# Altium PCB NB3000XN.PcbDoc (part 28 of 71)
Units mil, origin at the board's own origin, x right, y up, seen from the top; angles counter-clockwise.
Board outline 9527.56 x 6929.77 mil, 6 copper layers (Top Layer, GND+SHIELD, MidLayer1, MidLayer2, P2 - 3V3+5V0, Bottom Layer), stack 62.375 mil thick; 832 components, 1027 nets, 4655 pads, 4981 vias.
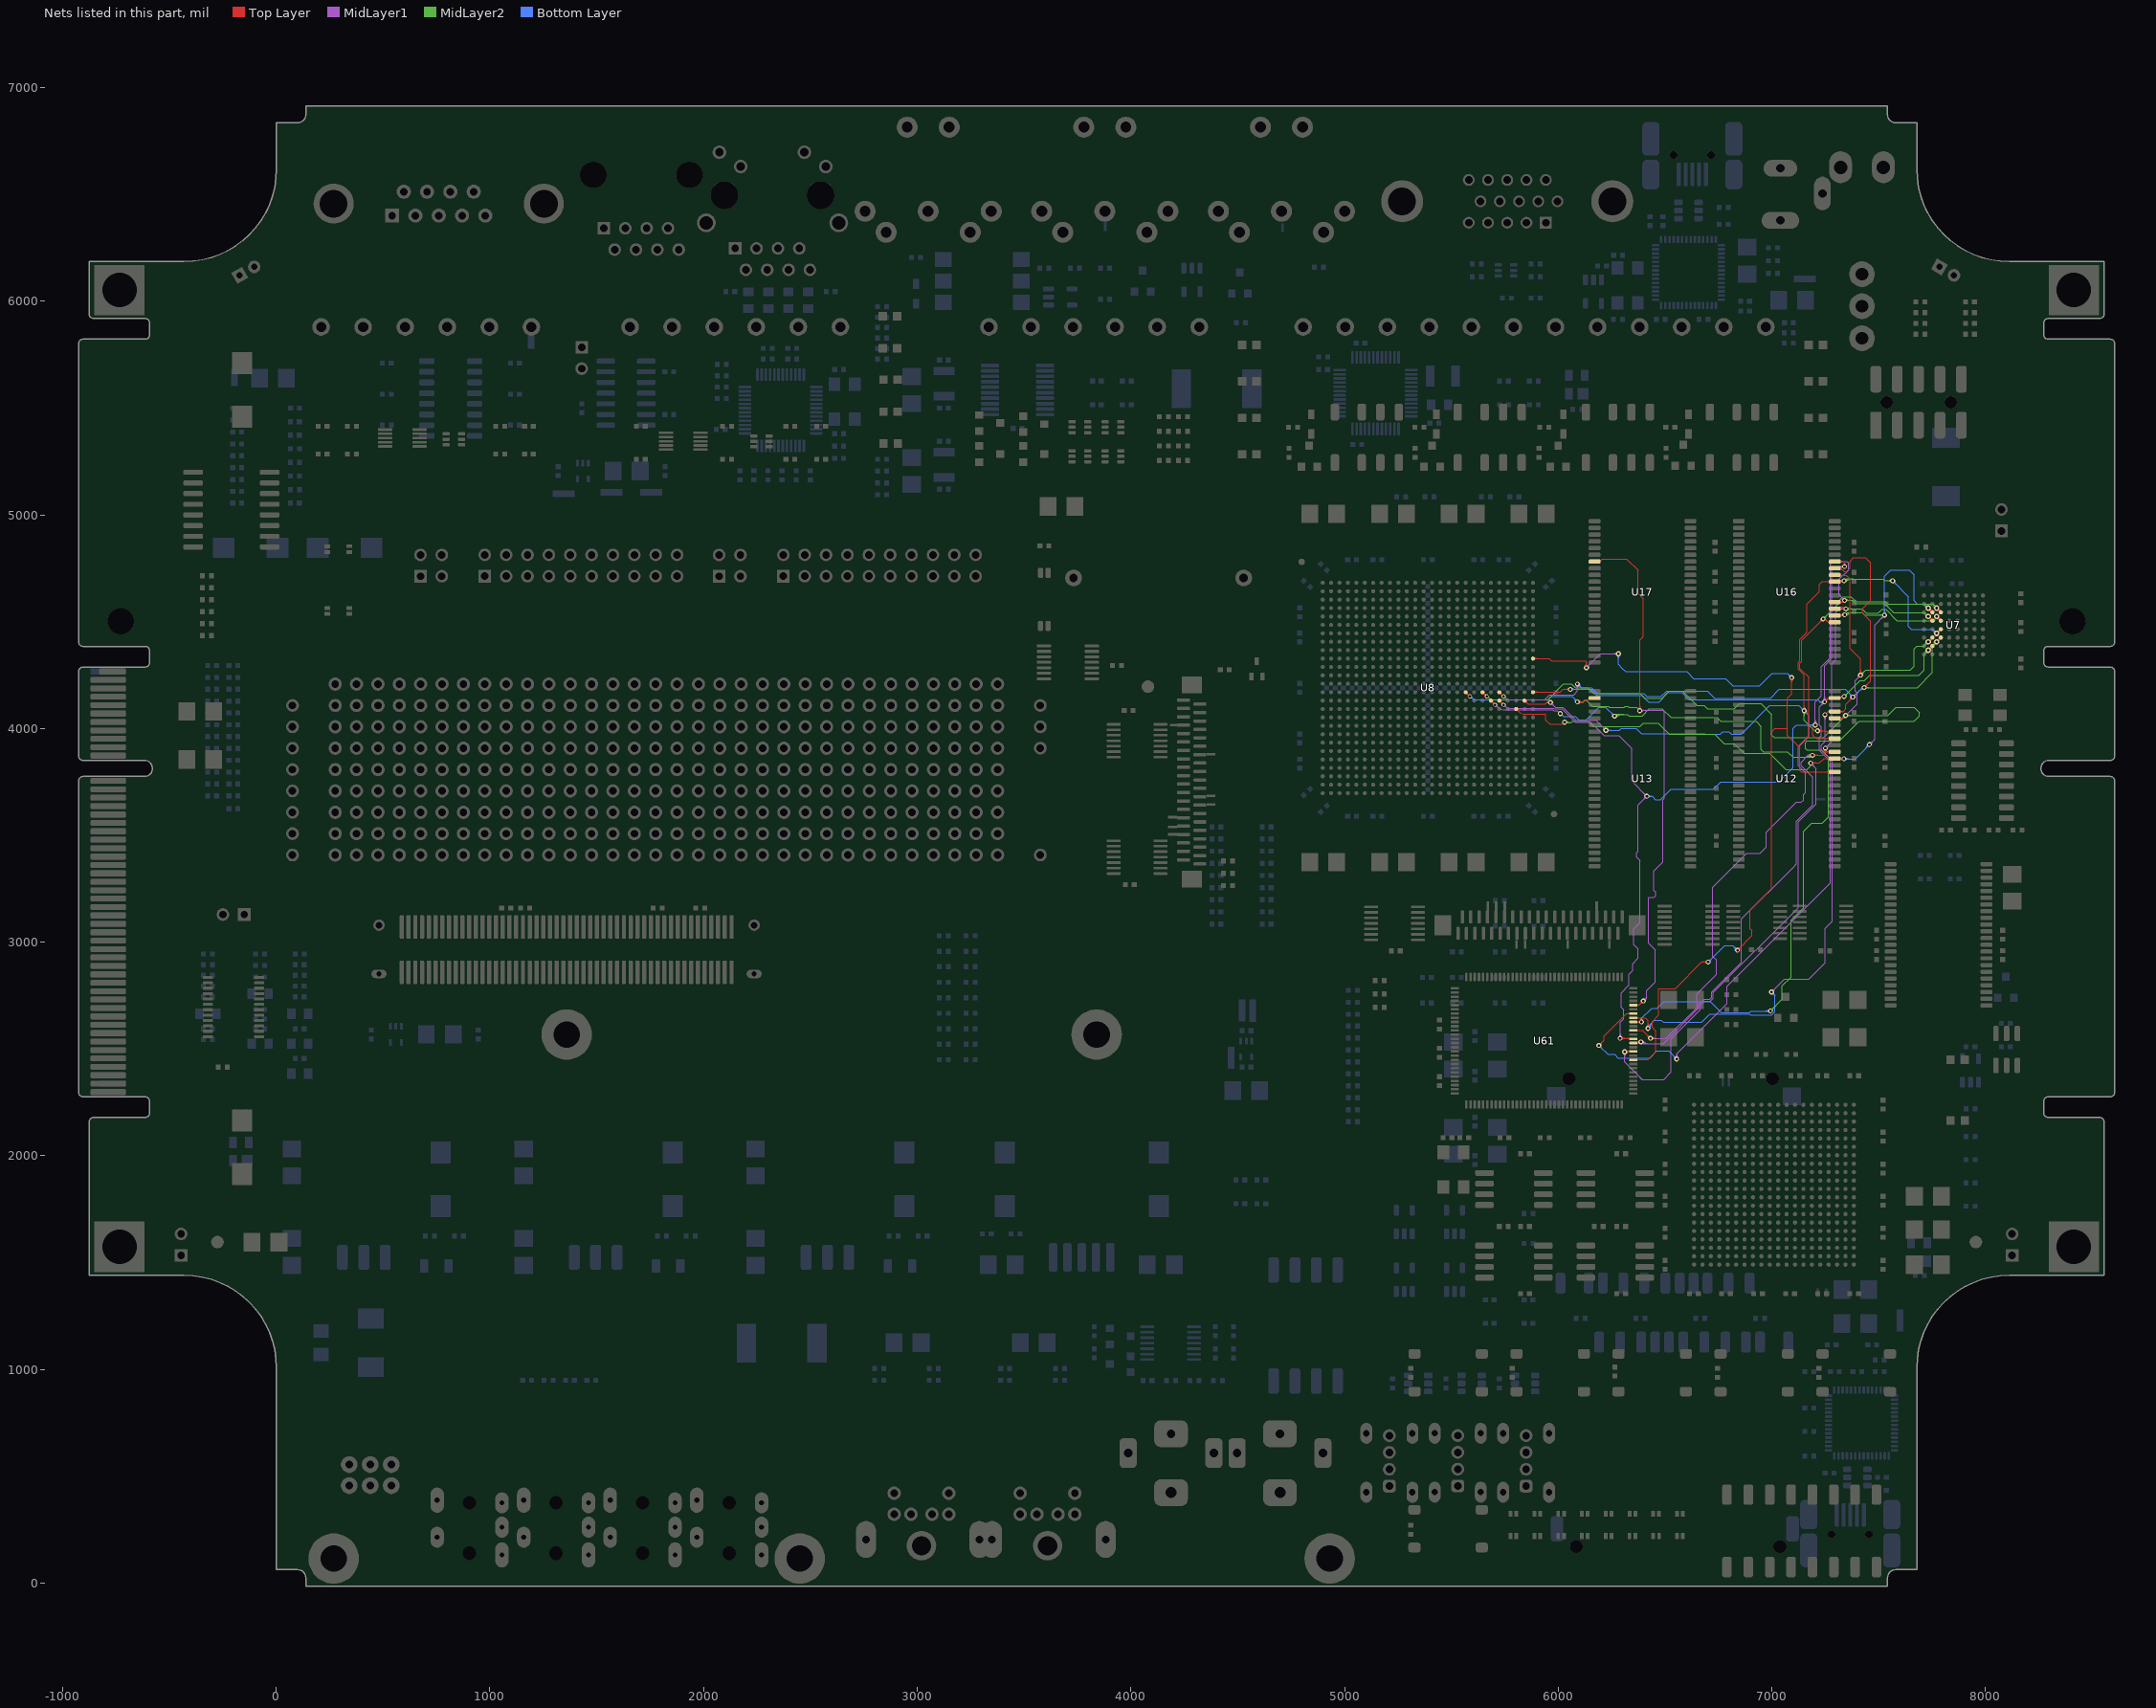
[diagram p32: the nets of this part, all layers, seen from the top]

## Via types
v1: diameter 23, hole 11.81, Top Layer to Bottom Layer, 3672 vias
v2: diameter 26, hole 11.81, Top Layer to Bottom Layer, 461 vias
v3: diameter 19, hole 11.81, Top Layer to Bottom Layer, tented both sides, 396 vias
v4: diameter 23.62, hole 11.81, Top Layer to Bottom Layer, 288 vias
v5: diameter 20, hole 11.81, Top Layer to Bottom Layer, 91 vias
v6: diameter 23, hole 11.81, Top Layer to Bottom Layer, tented both sides, 50 vias
v7: diameter 31, hole 11.81, Top Layer to Bottom Layer, 15 vias
v8: diameter 27.56, hole 11.81, Top Layer to Bottom Layer, tented both sides, 4 vias
v9: diameter 29, hole 11.81, Top Layer to Bottom Layer, 3 vias
v10: diameter 21, hole 11.81, Top Layer to Bottom Layer, 1 vias

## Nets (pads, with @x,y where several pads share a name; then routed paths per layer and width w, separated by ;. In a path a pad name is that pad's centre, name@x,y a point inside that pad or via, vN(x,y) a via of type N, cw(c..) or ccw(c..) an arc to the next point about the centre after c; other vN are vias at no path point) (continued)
DB_MEM.BUS_D8: U7.F3 U8.K26 U12.42 U16.29 U61.47 | length 6471.7
  Top Layer w4: U8.K26@5882.13,4327.8 5910,4327.8 5920,4327.8 5957.5,4327.8 5968.42,4316.87 6128.13,4316.87 6131.86,4313.14 v1(6131.86,4284.37) ; U8.K26@5887.43,4322.49 cw(c5900.23,4309.69) 5900.23,4327.8 cw(c5900.23,4345.9) U8.K26@5887.43,4333.1 ; v1@6125.14,4291.09 ccw(c6108.92,4307.31) 6131.86,4307.31 ccw(c6154.79,4307.31) v1@6138.57,4291.09 ; v1@6127.97,4288.26 ccw(c6118.58,4297.65) 6131.86,4297.65 ccw(c6145.14,4297.65) v1@6135.75,4288.26 ; U61.47@6356.86,2450.04 6420.04,2450.04 6456.86,2486.86 6456.86,2583.37 6440.19,2600.04 6440.19,2627.37 6471.19,2658.37 6471.19,2781.71 6472.86,2783.37 6548.52,2783.37 6672.52,2907.37 v1(6702.19,2907.37) ; U61.47@6367.95,2446.63 cw(c6376.19,2438.39) 6376.19,2450.04 ; U61.47@6367.95,2452.28 ccw(c6373.37,2457.7) 6373.37,2450.04 ; v1@6695.47,2900.66 ccw(c6679.26,2884.44) 6679.26,2907.37 ccw(c6679.26,2930.31) v1@6695.47,2914.09 ; v1@6698.3,2903.49 ccw(c6688.91,2894.1) 6688.91,2907.37 ccw(c6688.91,2920.65) v1@6698.3,2911.26 ; v1(6838.86,2962.37) 6906.86,3030.37 6906.86,3055 6898.52,3063.33 6898.52,3150.04 6998.52,3250.04 6998.52,3983.37 7015.19,4000.04 7073.52,4000.04 ; v1@6838.86,2967.87 ccw(c6838.86,2981.15) 6848.25,2971.76 ccw(c6857.64,2962.37) v1@6844.36,2962.37 ; v1@6838.86,2971.87 ccw(c6838.86,2994.81) 6855.07,2978.59 ccw(c6871.29,2962.37) v1@6848.36,2962.37 ; v1@7086.47,4231.99 cw(c7070.26,4215.77) 7093.19,4215.77 cw(c7116.13,4215.77) v1@7099.91,4231.99 ; v1@7089.3,4234.82 cw(c7079.91,4225.43) 7093.19,4225.43 cw(c7106.47,4225.43) v1@7097.08,4234.82 ; v1(7093.19,4238.71) 7093.19,4161.37 7073.52,4141.71 7073.52,4000.04 ; v1@7230.69,4513.04 cw(c7207.76,4513.04) 7223.97,4496.82 cw(c7240.19,4480.61) v1@7240.19,4503.54 ; v1@7234.69,4513.04 cw(c7221.41,4513.04) 7230.8,4503.65 cw(c7240.19,4494.26) v1@7240.19,4507.54 ; v1@7240.33,4511.55 cw(c7242.12,4492.78) 7255.45,4506.11 ; v1@7240.71,4507.57 cw(c7243.17,4481.82) 7261.46,4500.11 ; U16.29@7269.85,4494.4 ccw(c7263.3,4490.79) 7263.3,4498.27 ; U16.29@7269.85,4502.13 cw(c7263.3,4505.75) 7263.3,4498.27 ; U12.42@7271.19,3790.84 ccw(c7257.54,3777.18) 7257.54,3796.5 ccw(c7257.54,3815.81) U12.42@7271.19,3802.15 ; U12.42@7294.41,3796.5 7139.86,3796.5 7131.86,3804.5 7131.86,3908.37 ; U16.29@7294.41,4498.27 7263.3,4498.27 ; 5899.85,4327.8 ccw(c5899.85,4310.07) 5887.32,4322.6 cw(c5899.85,4310.07) 5899.85,4327.8 ; 5899.85,4327.8 cw(c5899.85,4345.52) 5887.32,4332.99 ccw(c5899.85,4345.52) 5899.85,4327.8 ; 7073.52,4000.04 7073.52,3966.71 7123.19,3917.04 ; 7123.19,3917.04 7131.86,3908.37 ; 7123.19,3917.04 7131.86,3908.37 ; 7123.19,3917.04 7173.52,3967.37 7173.52,4240.04 7131.86,4281.71 7131.86,4306.04 7140.19,4314.37 7140.19,4413.04 v1(7240.19,4513.04) 7248.52,4513.04 7263.3,4498.27
  Top Layer w8: v2@7771.26,4554.74 cw(c7771.26,4533.01) 7786.62,4548.38 cw(c7801.99,4563.74) v2@7780.26,4563.74 ; v2(7771.26,4563.74) U7.F3@7790.95,4544.06 ; U7.F3@7784.95,4544.06 ccw(c7770.46,4544.06) 7780.7,4554.3 ccw(c7790.95,4564.54) U7.F3@7790.95,4550.06
  MidLayer1 w4: v1(6131.86,4284.37) 6197.52,4350.04 v1(6281.86,4350.04) ; v1@6131.86,4289.87 ccw(c6131.86,4303.15) 6141.25,4293.76 ccw(c6150.64,4284.37) v1@6137.36,4284.37 ; v1@6131.86,4293.87 ccw(c6131.86,4316.81) 6148.07,4300.59 ccw(c6164.29,4284.37) v1@6141.36,4284.37 ; v1@6275.14,4343.32 ccw(c6258.92,4327.11) 6258.92,4350.04 ccw(c6258.92,4372.98) v1@6275.14,4356.76 ; v1@6277.97,4346.15 ccw(c6268.58,4336.76) 6268.58,4350.04 ccw(c6268.58,4363.32) v1@6277.97,4353.93
  MidLayer2 w4: v1(7240.19,4513.04) 7316.14,4588.99 7316.14,4601.99 7331.86,4617.71 7370.61,4617.71 7394.61,4593.71 7531.23,4593.71 7541.57,4583.37 7751.63,4583.37 v2(7771.26,4563.74) ; v1@7240.19,4518.54 ccw(c7240.19,4531.82) 7249.58,4522.43 ccw(c7258.97,4513.04) v1@7245.69,4513.04 ; v1@7240.19,4522.54 ccw(c7240.19,4545.48) 7256.41,4529.26 ccw(c7272.63,4513.04) v1@7249.69,4513.04 ; v2@7760.26,4563.74 ccw(c7733.7,4563.74) 7752.48,4582.52 ccw(c7771.26,4601.3) v2@7771.26,4574.74 ; v2@7764.26,4563.74 ccw(c7747.36,4563.74) 7759.31,4575.69 ccw(c7771.26,4587.64) v2@7771.26,4570.74
  Bottom Layer w4: v1@6275.14,4343.32 cw(c6258.92,4327.11) 6281.86,4327.11 cw(c6304.79,4327.11) v1@6288.57,4343.32 ; v1@6277.97,4346.15 cw(c6268.58,4336.76) 6281.86,4336.76 cw(c6295.14,4336.76) v1@6285.75,4346.15 ; v1(6281.86,4350.04) 6281.86,4300.04 6298.52,4283.37 6315.52,4266.37 6602.19,4266.37 6634.19,4234.37 6783.84,4234.37 6818.17,4200.04 6941.86,4200.04 7000.19,4258.37 7073.52,4258.37 v1(7093.19,4238.71) ; v1(6702.19,2907.37) 6774.52,2979.71 6778.52,2983.71 6817.52,2983.71 v1(6838.86,2962.37) ; v1@6702.19,2912.87 ccw(c6702.19,2926.15) 6711.58,2916.76 ccw(c6720.97,2907.37) v1@6707.69,2907.37 ; v1@6702.19,2916.87 ccw(c6702.19,2939.81) 6718.41,2923.59 ccw(c6734.63,2907.37) v1@6711.69,2907.37 ; v1@6829.36,2962.37 ccw(c6806.42,2962.37) 6822.64,2978.59 ccw(c6838.86,2994.81) v1@6838.86,2971.87 ; v1@6833.36,2962.37 ccw(c6820.08,2962.37) 6829.47,2971.76 ccw(c6838.86,2981.15) v1@6838.86,2967.87 ; v1@7083.69,4238.71 ccw(c7060.76,4238.71) 7076.97,4254.93 ccw(c7093.19,4271.14) v1@7093.19,4248.21 ; v1@7087.69,4238.71 ccw(c7074.41,4238.71) 7083.8,4248.1 ccw(c7093.19,4257.49) v1@7093.19,4244.21
DB_MEM.BUS_D9: U7.G3 U8.T24 U12.44 U16.30 U61.49 | length 6555.2
  Top Layer w4: U8.T24@5803.39,4084.23 cw(c5803.39,4066.51) 5815.92,4079.04 ; U8.T24@5810.73,4091.57 ccw(c5828.45,4091.57) 5815.92,4079.04 ; v1(6030,4030) 6020,4020 5961.9,4020 5942.36,4039.54 5942.36,4063.22 5937.86,4067.71 5920,4067.71 5910,4067.71 5843.27,4067.71 cw(c5843.27,4106.39) 5815.92,4079.04 ; v1(6311.19,2487.04) 6312.98,2488.83 U61.49@6351.93,2488.83 ; v1@6315.08,2483.15 cw(c6328.78,2469.45) 6328.78,2488.83 ; v1@6317.91,2480.32 cw(c6338.43,2459.8) U61.49@6338.43,2488.83 ; v1@6317.91,2493.76 ccw(c6329.82,2505.67) 6329.82,2488.83 ; U61.49@6335.91,2486 ccw(c6329.08,2479.17) 6329.08,2488.83 ccw(c6329.08,2498.48) U61.49@6335.91,2491.65 ; v1(7181.86,3838.71) 7223.71,3838.71 7244.49,3859.49 U12.44@7294.41,3859.49 ; v1@7185.75,3834.82 cw(c7195.14,3825.43) 7195.14,3838.71 cw(c7195.14,3851.99) v1@7185.75,3842.6 ; v1@7188.57,3831.99 cw(c7204.79,3815.77) 7204.79,3838.71 cw(c7204.79,3861.64) v1@7188.57,3845.43 ; U12.44@7271.19,3853.83 ccw(c7257.54,3840.17) 7257.54,3859.49 ccw(c7257.54,3878.8) U12.44@7271.19,3865.15 ; U12.44@7291.3,3859.49 7332.52,3859.49 7333.64,3858.37 v1(7337.52,3858.37) ; U16.30@7294.41,4529.76 7335.14,4529.76 7340.52,4524.37 v1(7340.52,4532.71) ; U16.30@7310.48,4529.76 ccw(c7310.48,4562.75) v1@7333.81,4539.43 ; U12.44@7311.9,3859.49 cw(c7311.9,3832.75) v1@7330.81,3851.66 ; U12.44@7317.28,3859.49 ccw(c7317.28,3878.62) v1@7330.81,3865.09 ; U12.44@7317.63,3853.83 cw(c7331.28,3840.18) 7331.28,3859.49 cw(c7331.28,3878.8) U12.44@7317.63,3865.15 ; U16.30@7317.63,4524.11 cw(c7331.28,4510.45) 7331.28,4529.76 cw(c7331.28,4549.08) U16.30@7317.63,4535.42 ; U16.30@7320.14,4529.76 ccw(c7320.14,4553.09) v1@7336.64,4536.6 ; U12.44@7321.56,3859.49 cw(c7321.56,3842.41) v1@7333.64,3854.49 ; 7324.7,4529.76 cw(c7324.7,4516.88) v1@7333.81,4525.99
  Top Layer w8: v2@7731.89,4554.74 cw(c7731.89,4533.01) 7747.25,4548.38 cw(c7762.62,4563.74) v2@7740.89,4563.74 ; v2(7731.89,4563.74) U7.G3@7751.58,4544.06 ; U7.G3@7745.58,4544.06 ccw(c7731.09,4544.06) 7741.33,4554.3 ccw(c7751.58,4564.54) U7.G3@7751.58,4550.06
  MidLayer1 w4: v1@6304.47,2480.32 cw(c6288.26,2464.11) 6311.19,2464.11 cw(c6334.13,2464.11) v1@6317.91,2480.32 ; v1@6306.86,2482.71 v1(6311.19,2487.04) 6311.19,2438.81 6391.63,2358.37 ; v1@6307.3,2483.15 cw(c6297.91,2473.76) 6311.19,2473.76 cw(c6324.47,2473.76) v1@6315.08,2483.15 ; 6381.4,2368.6 6391.96,2358.04 6493.88,2358.04 6529.19,2393.35 6529.19,2547.37 6665.19,2683.37 6665.19,2705.39 6685.17,2725.37 6712.84,2725.37 ; 6695.19,2725.04 6712.5,2725.04 6712.84,2725.37 ; v1@7181.86,3829.21 cw(c7181.86,3806.27) 7198.07,3822.49 cw(c7214.29,3838.71) v1@7191.36,3838.71 ; v1@7181.86,3833.21 cw(c7181.86,3819.93) 7191.25,3829.32 cw(c7200.64,3838.71) v1@7187.36,3838.71 ; v1(7181.86,3838.71) 7206.86,3813.71 7206.86,3670 7206.86,3647.06 7123.52,3563.73 7123.52,3541.71 7123.52,3535 7123.52,3161.37 6725.86,2763.71 6725.86,2738.39 6712.84,2725.37 ; v1(7456.86,3925.04) 7481.86,3950.04 7481.86,4484.71 v1(7527.86,4530.71) ; v1@7456.86,3930.54 ccw(c7456.86,3943.82) 7466.25,3934.43 ccw(c7475.64,3925.04) v1@7462.36,3925.04 ; v1@7456.86,3934.54 ccw(c7456.86,3957.48) 7473.07,3941.26 ccw(c7489.29,3925.04) v1@7466.36,3925.04 ; v1@7518.36,4530.71 cw(c7495.42,4530.71) 7511.64,4514.49 cw(c7527.86,4498.27) v1@7527.86,4521.21 ; v1@7522.36,4530.71 cw(c7509.08,4530.71) 7518.47,4521.32 cw(c7527.86,4511.93) v1@7527.86,4525.21
  MidLayer2 w4: v1(6030,4030) 6040,4030 6041.29,4028.71 6060.52,4028.71 6065.19,4033.37 6140.19,4033.37 6163.19,4010.37 6382.52,4010.37 6397.52,4025.37 6467.67,4025.37 6518.33,3974.71 6732.19,3974.71 6776.9,3930 6825,3930 6871.63,3883.37 6990.19,3883.37 7065.19,3808.37 7165.19,3808.37 7181.86,3825.04 v1(7181.86,3838.71) ; v1@6033.89,4033.89 ccw(c6046.4,4046.4) 6046.4,4028.71 ; v1@6036.72,4023.28 cw(c6049.82,4010.18) 6049.82,4028.71 ; v1@6036.72,4036.72 ccw(c6056.05,4056.05) 6056.05,4028.71 ; v1@7338.76,4534.48 cw(c7356.22,4517.02) 7356.22,4541.71 ; v1(7340.52,4532.71) 7349.52,4541.71 7423.52,4541.71 7434.52,4530.71 v1(7527.86,4530.71) ; v1@7341.58,4531.65 cw(c7365.87,4507.36) 7365.87,4541.71 ; v1@7344.41,4528.82 cw(c7375.53,4497.7) 7375.53,4541.71 ; v1@7347.24,4525.99 cw(c7385.19,4488.04) 7385.19,4541.71 ; v1@7521.14,4523.99 ccw(c7504.92,4507.77) 7504.92,4530.71 ccw(c7504.92,4553.64) v1@7521.14,4537.43 ; v1@7523.97,4526.82 ccw(c7514.58,4517.43) 7514.58,4530.71 ccw(c7514.58,4543.99) v1@7523.97,4534.6
  Bottom Layer w4: v1(7337.52,3858.37) 7390.19,3858.37 v1(7456.86,3925.04) ; v1@7341.41,3854.49 cw(c7350.8,3845.1) 7350.8,3858.37 cw(c7350.8,3871.65) v1@7341.41,3862.26 ; v1@7344.24,3851.66 cw(c7360.46,3835.44) 7360.46,3858.37 cw(c7360.46,3881.31) v1@7344.24,3865.09 ; v1@7447.36,3925.04 cw(c7424.42,3925.04) 7440.64,3908.82 cw(c7456.86,3892.61) v1@7456.86,3915.54 ; v1@7451.36,3925.04 cw(c7438.08,3925.04) 7447.47,3915.65 cw(c7456.86,3906.26) v1@7456.86,3919.54 ; v1@7521.14,4537.43 ccw(c7504.92,4553.64) 7527.86,4553.64 ccw(c7550.79,4553.64) v1@7534.57,4537.43 ; v1@7523.97,4534.6 ccw(c7514.58,4543.99) 7527.86,4543.99 ccw(c7541.14,4543.99) v1@7531.75,4534.6 ; v1(7527.86,4530.71) 7527.86,4712.71 7556.86,4741.71 7644.19,4741.71 7665.19,4720.71 7665.19,4597.71 7679.52,4583.37 7712.26,4583.37 v2(7731.89,4563.74) ; v2@7720.89,4563.74 ccw(c7694.33,4563.74) 7713.11,4582.52 ccw(c7731.89,4601.3) v2@7731.89,4574.74 ; v2@7724.89,4563.74 ccw(c7707.99,4563.74) 7719.94,4575.69 ccw(c7731.89,4587.64) v2@7731.89,4570.74
DB_MEM.BUS_D10: U7.F4 U8.R21 U12.45 U16.31 U61.51 | length 6324.8
  Top Layer w4: U8.R21@5685.28,4123.44 cw(c5685.28,4105.34) 5698.08,4118.14 cw(c5710.88,4130.94) U8.R21@5692.78,4130.94 ; U8.R21@5685.28,4123.6 cw(c5685.28,4105.88) 5697.81,4118.41 cw(c5710.34,4130.94) U8.R21@5692.62,4130.94 ; U8.R21@5685.28,4130.94 v3(5704.96,4111.26) ; U61.51@6361.54,2528.2 ccw(c6361.54,2558.84) v1@6383.29,2537.25 ; U61.51@6367.95,2525.37 cw(c6374.78,2518.54) 6374.78,2528.2 cw(c6374.78,2537.85) U61.51@6367.95,2531.02 ; 6371.15,2528.2 ccw(c6371.15,2549.3) v1@6386.13,2534.43 ; 6376.76,2528.2 cw(c6376.76,2522.94) v1@6380.47,2526.66 ; v1@6380.45,2540.07 cw(c6351.93,2568.37) U61.51@6351.93,2528.2 v1@6384.04,2528.2 ; v1(7190.19,3875.04) 7241.25,3875.04 7250.52,3884.32 ; v1@7194.08,3871.15 cw(c7203.47,3861.76) 7203.47,3875.04 cw(c7203.47,3888.32) v1@7194.08,3878.93 ; v1@7196.91,3868.32 cw(c7213.13,3852.11) 7213.13,3875.04 cw(c7213.13,3897.98) v1@7196.91,3881.76 ; v1@7243.81,3901.66 cw(c7227.59,3885.44) 7250.52,3885.44 cw(c7273.46,3885.44) v1@7257.24,3901.66 ; v1@7246.64,3904.49 cw(c7237.25,3895.1) 7250.52,3895.1 cw(c7263.8,3895.1) v1@7254.41,3904.49 ; v1(7250.52,3908.37) 7250.52,3884.32 ; U12.45@7271.19,3885.33 ccw(c7257.54,3871.67) 7257.54,3890.98 ccw(c7257.54,3910.3) U12.45@7271.19,3896.64 ; U12.45@7294.41,3890.98 7257.19,3890.98 7250.52,3884.32 ; U16.31@7299.86,4566.71 v1@7340.52,4566.71 ; U16.31@7308.16,4566.71 cw(c7308.16,4521.01) v1@7340.47,4553.32 ; U16.31@7311.97,4561.26 cw(c7323.54,4551.7) 7323.54,4566.71 ; U16.31@7315.05,4558.71 cw(c7332.03,4544.69) 7332.03,4566.71 ; U16.31@7317.82,4566.71 cw(c7317.82,4530.67) v1@7343.3,4556.15 ; U16.31@7318.14,4556.16 cw(c7340.52,4537.67) v1@7340.52,4566.71 ; 7327.47,4566.71 cw(c7327.47,4540.32) v1@7346.13,4558.98 ; 7337.13,4566.71 cw(c7337.13,4549.98) v1@7348.96,4561.81 ; v1(7347.19,4560.04) v1@7340.52,4566.71 ; 5692.16,4124.06 cw(c5679.35,4111.26) 5697.46,4111.26 ccw(c5679.35,4111.26) 5692.16,4124.06 ; 5692.16,4124.06 ccw(c5704.96,4136.87) 5704.96,4118.76 cw(c5704.96,4136.87) 5692.16,4124.06
  Top Layer w8: v2@7771.26,4515.37 cw(c7771.26,4493.64) 7786.62,4509.01 cw(c7801.99,4524.37) v2@7780.26,4524.37 ; v2(7771.26,4524.37) U7.F4@7790.95,4504.69 ; U7.F4@7784.95,4504.69 ccw(c7770.46,4504.69) 7780.7,4514.93 ccw(c7790.95,4525.17) U7.F4@7790.95,4510.69
  MidLayer1 w4: v3@5705.61,4103.79 cw(c5707.19,4085.75) 5718.83,4099.62 ; v3@5712.43,4111.91 ccw(c5730.47,4113.49) 5718.83,4099.62 ; 5781.77,4087.4 5767.84,4087.4 ; v1@6010.54,4071.35 6010,4070.81 v1(6010,4070) 5996.29,4083.71 5979.9,4083.71 5976.21,4087.4 5924.74,4087.4 5920,4087.4 5910,4087.4 5861.38,4087.4 5841.96,4087.4 5767.84,4087.4 ; v1@6385.42,2531.61 ccw(c6401.27,2547.46) 6401.27,2525.04 ; v1(6387.19,2533.37) 6395.52,2525.04 6491.86,2525.04 6656.86,2690.04 6656.86,2708.37 6681.86,2733.37 6709.52,2733.37 6717.86,2741.71 6717.86,2767.02 6856.86,2906.02 6856.86,3108.37 7098.52,3350.04 7115.52,3367.04 7115.52,3567.04 ; v1@6388.25,2534.44 ccw(c6410.93,2557.12) 6410.93,2525.04 ; v1@6391.08,2537.26 ccw(c6420.59,2566.77) 6420.59,2525.04 ; v1@6393.91,2540.09 ccw(c6430.25,2576.43) 6430.25,2525.04 ; v1@7182.9,3868.95 ccw(c7169.86,3858.03) 7169.86,3875.04 ; v1@7182.9,3881.14 cw(c7169.86,3892.05) 7169.86,3875.04 ; v1@7185.97,3871.51 ccw(c7178.42,3865.19) 7178.42,3875.04 ccw(c7178.42,3884.89) v1@7185.97,3878.57 ; v1(7190.19,3875.04) 7169.86,3875.04 ; v1(7250.52,3908.37) 7281.86,3939.71 7281.86,4303.33 7298.52,4320 7298.52,4541.71 7316.86,4560.04 v1(7347.19,4560.04) ; v1@7250.52,3913.87 ccw(c7250.52,3927.15) 7259.91,3917.76 ccw(c7269.3,3908.37) v1@7256.02,3908.37 ; v1@7250.52,3917.87 ccw(c7250.52,3940.81) 7266.74,3924.59 ccw(c7282.96,3908.37) v1@7260.02,3908.37 ; v1@7340.47,4553.32 ccw(c7324.26,4537.11) 7324.26,4560.04 ccw(c7324.26,4582.98) v1@7340.47,4566.76 ; v1@7343.3,4556.15 ccw(c7333.91,4546.76) 7333.91,4560.04 ccw(c7333.91,4573.32) v1@7343.3,4563.93 ; 5718.83,4099.62 ccw(c5748.34,4129.13) 5748.34,4087.4 5767.84,4087.4 ; 7115.52,3567.04 7190.19,3641.71 ; 7115.52,3567.04 7190.19,3641.71 ; 7169.86,3875.04 7136.52,3841.71 7136.52,3825.04 7190.19,3771.37 7190.19,3641.71
  MidLayer2 w4: v1@6262.42,4060.14 cw(c6278.27,4044.29) 6278.27,4066.71 ; v1(6264.19,4058.37) 6272.52,4066.71 6323.52,4066.71 6330.23,4060 6393.52,4060 6425.91,4092.38 6486.54,4092.38 6527.54,4051.37 6685,4051.37 6743.86,4051.37 6761.86,4033.37 6926.63,4033.37 6950,4010 6950,3901.71 6960,3891.71 7073.52,3891.71 7098.52,3866.71 7181.86,3866.71 v1(7190.19,3875.04) ; v1@6265.25,4057.31 cw(c6287.93,4034.64) 6287.93,4066.71 ; v1@6268.08,4054.49 cw(c6297.59,4024.98) 6297.59,4066.71 ; v1@6270.91,4051.66 cw(c6307.24,4015.32) 6307.24,4066.71 ; 7147.14,3866.71 ccw(c7147.14,3918.09) v1@7183.47,3881.76 ; 7156.79,3866.71 ccw(c7156.79,3908.44) v1@7186.3,3878.93 ; 7166.45,3866.71 ccw(c7166.45,3898.78) v1@7189.13,3876.1 ; 7176.11,3866.71 ccw(c7176.11,3889.12) v1@7191.96,3873.27 ; v1(7347.19,4560.04) 7421.86,4560.04 7441.52,4540.37 7497.19,4540.37 7515.04,4558.23 7532.77,4558.23 7585.96,4505.04 7760.19,4505.04 7765.19,4510.04 v2@7765.19,4524.37 ; v1@7351.08,4556.15 cw(c7360.47,4546.76) 7360.47,4560.04 cw(c7360.47,4573.32) v1@7351.08,4563.93 ; v1@7353.91,4553.32 cw(c7370.13,4537.11) 7370.13,4560.04 cw(c7370.13,4582.98) v1@7353.91,4566.76
  Bottom Layer w4: v1(6010,4070) 6010,4070.81 6010.54,4071.35 6024.71,4057.19 6079.71,4057.19 6095.19,4041.71 6131.86,4041.71 6190.19,4100.04 6222.52,4100.04 v1(6264.19,4058.37) ; v1@6254.69,4058.37 ccw(c6231.76,4058.37) 6247.97,4074.59 ccw(c6264.19,4090.81) v1@6264.19,4067.87 ; v1@6258.69,4058.37 ccw(c6245.41,4058.37) 6254.8,4067.76 ccw(c6264.19,4077.15) v1@6264.19,4063.87
DB_MEM.BUS_D11: U7.G4 U8.R22 U12.47 U16.32 U61.52 | length 5865.6
  Top Layer w4: U8.R22@5724.65,4123.44 cw(c5724.65,4105.34) 5737.45,4118.14 cw(c5750.25,4130.94) U8.R22@5732.15,4130.94 ; U8.R22@5724.65,4123.6 cw(c5724.65,4105.88) 5737.18,4118.41 cw(c5749.71,4130.94) U8.R22@5731.99,4130.94 ; U8.R22@5724.65,4130.94 v3(5744.33,4111.26) ; v1(6290.19,2550.04) U61.52@6351.93,2550.04 ; v1@6294.08,2546.15 cw(c6303.47,2536.76) 6303.47,2550.04 cw(c6303.47,2563.32) v1@6294.08,2553.93 ; v1@6296.91,2543.32 cw(c6313.13,2527.11) 6313.13,2550.04 cw(c6313.13,2572.98) v1@6296.91,2556.76 ; 6323.87,2550.04 cw(c6323.87,2533.01) U61.52@6335.91,2545.05 ; v1(7203.52,4016.71) 7190.19,4003.37 7190.19,3969.81 7206.02,3953.98 U12.47@7294.41,3953.98 ; U12.47@7271.19,3948.32 ccw(c7257.54,3934.66) 7257.54,3953.98 ccw(c7257.54,3973.29) U12.47@7271.19,3959.63 ; U16.32@7294.41,4592.76 7323.14,4592.76 ; U16.32@7311.97,4592.76 cw(c7317.53,4586.17) 7323.64,4592.26 ; U16.32@7319.54,4590.18 cw(c7323.14,4588.95) 7323.14,4592.76 ; U16.32@7319.54,4595.33 ccw(c7323.14,4596.56) 7323.14,4592.76 ; v1(7340.19,4600.04) 7331.86,4591.71 7324.19,4591.71 7323.14,4592.76 ; 5731.53,4124.06 cw(c5718.72,4111.26) 5736.83,4111.26 ccw(c5718.72,4111.26) 5731.53,4124.06 ; 5731.53,4124.06 ccw(c5744.33,4136.87) 5744.33,4118.76 cw(c5744.33,4136.87) 5731.53,4124.06
  Top Layer w8: v2@7731.89,4515.37 cw(c7731.89,4493.64) 7747.25,4509.01 cw(c7762.62,4524.37) v2@7740.89,4524.37 ; v2(7731.89,4524.37) U7.G4@7751.58,4504.69 ; U7.G4@7745.58,4504.69 ccw(c7731.09,4504.69) 7741.33,4514.93 ccw(c7751.58,4525.17) U7.G4@7751.58,4510.69
  MidLayer1 w4: v3@5744.98,4103.79 cw(c5746.56,4085.75) 5758.2,4099.62 cw(c5769.84,4113.49) v3@5751.8,4111.91 ; 5757.91,4099.87 ccw(c5767.84,4109.8) 5767.84,4095.75 5861.38,4095.75 5910,4095.75 5920,4095.75 5924.74,4095.75 5979.17,4095.75 5983.21,4091.71 6018.52,4091.71 6073.66,4036.57 6080.36,4029.87 6152.75,4029.87 6195.62,3987.01 6195.62,3986.28 6215.19,3966.71 6283.86,3966.71 6344.52,3906.04 6344.52,3754.04 v1(6415.19,3683.37) 6373.52,3641.71 6373.52,3425.04 6367.19,3418.71 6367.19,3397.81 6382.86,3382.14 6382.86,3091.71 6353.52,3062.37 6353.52,2989.08 6373.52,2969.08 6373.52,2925.04 6348.52,2900.04 6348.52,2866.71 6331.86,2850.04 6331.86,2800.04 6295,2763.18 6295,2695.23 6306.86,2683.37 6306.86,2641.71 6290.19,2625.04 v1(6290.19,2550.04) ; v1@6283.47,2556.76 ccw(c6267.26,2572.98) 6290.19,2572.98 ccw(c6313.13,2572.98) v1@6296.91,2556.76 ; v1@6286.3,2553.93 ccw(c6276.91,2563.32) 6290.19,2563.32 ccw(c6303.47,2563.32) v1@6294.08,2553.93 ; v1@6415.19,3673.87 ccw(c6415.19,3650.94) 6398.97,3667.16 ccw(c6382.76,3683.37) 6405.69,3683.37 ccw(c6382.76,3683.37) 6398.97,3699.59 ccw(c6415.19,3715.81) v1@6415.19,3692.87 ; v1@6415.19,3677.87 ccw(c6415.19,3664.6) 6405.8,3673.99 ccw(c6396.41,3683.37) 6409.69,3683.37 ccw(c6396.41,3683.37) 6405.8,3692.76 ccw(c6415.19,3702.15) v1@6415.19,3688.87 ; v1@7196.81,4023.43 ccw(c7180.59,4039.64) 7203.52,4039.64 ccw(c7226.46,4039.64) v1@7210.24,4023.43 ; v1@7199.64,4020.6 ccw(c7190.25,4029.99) 7203.52,4029.99 ccw(c7216.8,4029.99) v1@7207.41,4020.6 ; v1(7203.52,4016.71) 7203.52,4125.04 7231.86,4153.37 7231.86,4290.37 7273.52,4332.04 7273.52,4768.04 7288.86,4783.37 7349.86,4783.37 7358.19,4775.04 7358.19,4741.71 7315.19,4698.71 7315.19,4625.04 v1(7340.19,4600.04) ; v1@7330.69,4600.04 ccw(c7307.76,4600.04) 7323.97,4616.26 ccw(c7340.19,4632.48) v1@7340.19,4609.54 ; v1@7334.69,4600.04 ccw(c7321.41,4600.04) 7330.8,4609.43 ccw(c7340.19,4618.82) v1@7340.19,4605.54
  MidLayer2 w4: v1(7340.19,4600.04) 7372,4600.04 7377,4600 7391.29,4585.71 7527.92,4585.71 7569.92,4543.71 7712.55,4543.71 v2(7731.89,4524.37) ; v1@7344.08,4596.15 cw(c7353.47,4586.76) 7353.47,4600.04 cw(c7353.47,4613.32) v1@7344.08,4603.93 ; v1@7346.91,4593.32 cw(c7363.13,4577.11) 7363.13,4600.04 cw(c7363.13,4622.98) v1@7346.91,4606.76 ; v2@7720.89,4524.37 ccw(c7694.33,4524.37) 7713.11,4543.15 ccw(c7731.89,4561.93) v2@7731.89,4535.37 ; v2@7724.89,4524.37 ccw(c7707.99,4524.37) 7719.94,4536.32 ccw(c7731.89,4548.27) v2@7731.89,4531.37
  Bottom Layer w4: v1(6415.19,3683.37) 6440.19,3683.37 6455.48,3668.09 6479.55,3668.09 6527.5,3716.04 6725.84,3716.04 6760.5,3750.71 7032.52,3750.71 7098.52,3816.71 7098.52,4000.04 7115.19,4016.71 v1(7203.52,4016.71) ; v1@6419.08,3679.49 cw(c6428.47,3670.1) 6428.47,3683.37 cw(c6428.47,3696.65) v1@6419.08,3687.26 ; v1@6421.91,3676.66 cw(c6438.13,3660.44) 6438.13,3683.37 cw(c6438.13,3706.31) v1@6421.91,3690.09 ; v1@7196.81,4009.99 ccw(c7180.59,3993.77) 7180.59,4016.71 ccw(c7180.59,4039.64) v1@7196.81,4023.43 ; v1@7199.64,4012.82 ccw(c7190.25,4003.43) 7190.25,4016.71 ccw(c7190.25,4029.99) v1@7199.64,4020.6
DB_MEM.BUS_D12: U7.F5 U8.R25 U12.48 U16.35 U61.54 | length 6312.6
  Top Layer w4: U8.R25@5842.76,4123.6 cw(c5842.76,4105.88) 5855.29,4118.41 ; U8.R25@5850.1,4130.94 ccw(c5867.83,4130.94) 5855.29,4118.41 ; v1@5955.85,4117.26 ccw(c5946.52,4111.31) 5946.52,4122.37 ; v1@5955.85,4127.49 cw(c5946.52,4133.44) 5946.52,4122.37 ; v1(5963.86,4122.37) 5946.52,4122.37 ; U61.54@6351.93,2587.25 6394.65,2587.25 v1(6431.86,2550.04) v1@6431.86,2558.37 ; U61.54@6367.95,2584.42 cw(c6374.78,2577.59) 6374.78,2587.25 cw(c6374.78,2596.91) U61.54@6367.95,2590.08 ; v1@6422.36,2550.04 ccw(c6399.42,2550.04) 6415.64,2566.26 ccw(c6431.86,2582.48) v1@6431.86,2559.54 ; v1@6426.36,2550.04 ccw(c6413.08,2550.04) 6422.47,2559.43 ccw(c6431.86,2568.82) v1@6431.86,2555.54 ; v1@7144.81,4090.09 ccw(c7128.59,4106.31) 7151.52,4106.31 ccw(c7174.46,4106.31) v1@7158.24,4090.09 ; v1@7147.64,4087.26 ccw(c7138.25,4096.65) 7151.52,4096.65 ccw(c7164.8,4096.65) v1@7155.41,4087.26 ; v1(7151.52,4083.37) 7151.52,4250.73 7123.52,4278.73 7123.52,4309.02 7131.86,4317.36 7131.86,4416.71 7165.19,4450.04 7165.19,4583.37 7223.52,4641.71 7223.52,4675.04 7235.73,4687.24 U16.35@7294.41,4687.24 7333.73,4687.24 v1(7338.19,4691.71) ; v1(7214.19,3989.71) 7252.29,3989.71 7256.52,3985.47 U12.48@7294.41,3985.47 ; v1@7218.08,3985.82 cw(c7227.47,3976.43) 7227.47,3989.71 cw(c7227.47,4002.99) v1@7218.08,3993.6 ; v1@7220.91,3982.99 cw(c7237.13,3966.77) 7237.13,3989.71 cw(c7237.13,4012.64) v1@7220.91,3996.43 ; U12.48@7271.19,3979.82 ccw(c7257.54,3966.16) 7257.54,3985.47 ccw(c7257.54,4004.79) U12.48@7271.19,3991.13 ; U16.35@7271.19,4681.59 ccw(c7257.54,4667.93) 7257.54,4687.24 ccw(c7257.54,4706.56) U16.35@7271.19,4692.9 ; U16.35@7304.48,4687.24 ccw(c7304.48,4725.42) v1@7331.47,4698.43 ; U16.35@7314.13,4687.24 ccw(c7314.13,4715.76) v1@7334.3,4695.6 ; U16.35@7317.63,4681.59 cw(c7331.28,4667.93) 7331.28,4687.24 cw(c7331.28,4706.56) U16.35@7317.63,4692.9 ; 7323.79,4687.24 ccw(c7323.79,4706.11) v1@7337.13,4692.77 ; 7326.03,4687.24 cw(c7326.03,4679.55) v1@7331.47,4684.99 ; 5855.29,4118.41 ccw(c5862.47,4125.59) 5862.47,4115.44 5910,4115.44 5920,4115.44 5924.74,4115.44 5939.59,4115.44 5946.52,4122.37
  Top Layer w8: v2(7771.26,4445.63) U7.F5@7790.95,4465.32 ; v2@7771.26,4454.63 ccw(c7771.26,4476.36) 7786.62,4460.99 ccw(c7801.99,4445.63) v2@7780.26,4445.63 ; U7.F5@7784.95,4465.32 cw(c7770.46,4465.32) 7780.7,4455.07 cw(c7790.95,4444.83) U7.F5@7790.95,4459.32
  MidLayer1 w4: v1@5963.86,4112.87 cw(c5963.86,4089.94) 5980.07,4106.16 cw(c5996.29,4122.37) v1@5973.36,4122.37 ; v1@5963.86,4116.87 cw(c5963.86,4103.6) 5973.25,4112.99 cw(c5982.64,4122.37) v1@5969.36,4122.37 ; v1(5963.86,4122.37) 5986.19,4100.04 6021.52,4100.04 6083.69,4037.87 6177.36,4037.87 6181.19,4034.04 v1(6223.52,3991.71) ; v1@6214.02,3991.71 ccw(c6191.09,3991.71) 6207.31,4007.93 ccw(c6223.52,4024.14) v1@6223.52,4001.21 ; v1@6218.02,3991.71 ccw(c6204.75,3991.71) 6214.13,4001.1 ccw(c6223.52,4010.49) v1@6223.52,3997.21 ; v1(6431.86,2550.04) 6504.86,2550.04 6648.52,2693.71 6648.52,2758.37 6740.19,2850.04 6740.19,2916.71 6723.52,2933.37 6723.52,3258.37 6881.86,3416.71 6935,3416.71 6945.23,3416.71 6973.52,3445 6973.52,3513.73 7114.89,3655.09 7138.24,3655.09 7148.52,3665.37 7148.52,3691.71 7156.86,3700.04 7156.86,3791.71 7123.52,3825.04 7123.52,3913.37 7173.52,3963.37 7173.52,4061.37 v1(7151.52,4083.37) ; v1@6435.75,2546.15 cw(c6445.14,2536.76) 6445.14,2550.04 cw(c6445.14,2563.32) v1@6435.75,2553.93 ; v1@6438.57,2543.32 cw(c6454.79,2527.11) 6454.79,2550.04 cw(c6454.79,2572.98) v1@6438.57,2556.76 ; v1@7151.52,4073.87 cw(c7151.52,4050.94) 7167.74,4067.16 cw(c7183.96,4083.37) v1@7161.02,4083.37 ; v1@7151.52,4077.87 cw(c7151.52,4064.6) 7160.91,4073.99 cw(c7170.3,4083.37) v1@7157.02,4083.37
  MidLayer2 w4: v1@7144.81,4076.66 cw(c7128.59,4060.44) 7151.52,4060.44 cw(c7174.46,4060.44) v1@7158.24,4076.66 ; v1@7147.64,4079.49 cw(c7138.25,4070.1) 7151.52,4070.1 cw(c7164.8,4070.1) v1@7155.41,4079.49 ; v1(7151.52,4083.37) 7151.52,4038.71 7200.52,3989.71 v1(7214.19,3989.71) ; v1@7336.42,4693.48 cw(c7352.27,4677.63) 7352.27,4700.04 ; v1(7338.19,4691.71) 7346.52,4700.04 7520,4700.04 7528.33,4691.71 v1(7565.19,4691.71) ; v1@7339.25,4690.65 cw(c7361.93,4667.97) 7361.93,4700.04 ; v1@7342.08,4687.82 cw(c7371.59,4658.31) 7371.59,4700.04 ; v1@7344.91,4684.99 cw(c7381.24,4648.66) 7381.24,4700.04 ; v1@7558.47,4684.99 ccw(c7542.26,4668.77) 7542.26,4691.71 ccw(c7542.26,4714.64) v1@7558.47,4698.43 ; v1@7561.3,4687.82 ccw(c7551.91,4678.43) 7551.91,4691.71 ccw(c7551.91,4704.99) v1@7561.3,4695.6
  Bottom Layer w4: v1(6223.52,3991.71) 6286.67,3991.71 6295,4000.04 6365.19,4000.04 6390.19,3975.04 6686.86,3975.04 ; v1@6227.41,3987.82 cw(c6236.8,3978.43) 6236.8,3991.71 cw(c6236.8,4004.99) v1@6227.41,3995.6 ; v1@6230.24,3984.99 cw(c6246.46,3968.77) 6246.46,3991.71 cw(c6246.46,4014.64) v1@6230.24,3998.43 ; 6685,3975 6760,3975 6770,3985 6800,3985 6810,3975 6856.82,3975 6990.19,4108.37 7126.52,4108.37 v1(7151.52,4083.37) ; v1@7142.02,4083.37 ccw(c7119.09,4083.37) 7135.31,4099.59 ccw(c7151.52,4115.81) v1@7151.52,4092.87 ; v1@7146.02,4083.37 ccw(c7132.75,4083.37) 7142.14,4092.76 ccw(c7151.52,4102.15) v1@7151.52,4088.87 ; v1@7565.19,4682.21 cw(c7565.19,4659.27) 7581.41,4675.49 cw(c7597.63,4691.71) v1@7574.69,4691.71 ; v1@7565.19,4686.21 cw(c7565.19,4672.93) 7574.58,4682.32 cw(c7583.97,4691.71) v1@7570.69,4691.71 ; v1(7565.19,4691.71) 7640.19,4616.71 7640.19,4476.71 7651.52,4465.37 7751.52,4465.37 v2(7771.26,4445.63) ; v2@7760.26,4445.63 ccw(c7733.7,4445.63) 7752.48,4464.41 ccw(c7771.26,4483.19) v2@7771.26,4456.63 ; v2@7764.26,4445.63 ccw(c7747.36,4445.63) 7759.31,4457.58 ccw(c7771.26,4469.53) v2@7771.26,4452.63
DB_MEM.BUS_D13: U7.G6 U8.P20 U12.50 U16.36 U61.56 | length 7321.3
  Top Layer w4: U8.P20@5645.91,4162.81 cw(c5645.91,4144.71) 5658.71,4157.51 cw(c5671.51,4170.31) U8.P20@5653.41,4170.31 ; U8.P20@5645.91,4162.97 cw(c5645.91,4145.25) 5658.44,4157.78 cw(c5670.97,4170.31) U8.P20@5653.25,4170.31 ; U8.P20@5645.91,4170.31 v3(5665.59,4150.63) ; U61.56@6351.93,2626.62 6365.12,2626.61 6365.12,2626.71 v1(6390.19,2626.71) ; U61.56@6367.95,2623.79 cw(c6374.99,2616.75) 6374.99,2626.71 ; U61.56@6367.95,2629.45 ccw(c6374.57,2636.07) 6374.57,2626.71 ; v1@6383.47,2619.99 ccw(c6367.26,2603.77) 6367.26,2626.71 ccw(c6367.26,2649.64) v1@6383.47,2633.43 ; v1@6386.3,2622.82 ccw(c6376.91,2613.43) 6376.91,2626.71 ccw(c6376.91,2639.99) v1@6386.3,2630.6 ; U12.50@7294.41,4048.46 7332.28,4048.46 v1(7345.19,4061.37) ; U16.36@7294.41,4718.74 7306.86,4718.73 7306.86,4716.71 7348.52,4716.71 7365.19,4700.04 7365.19,4375.04 7415.19,4325.04 v1(7415.19,4250.04) ; U16.36@7314.8,4721.57 ccw(c7326.53,4733.3) 7326.53,4716.71 ; U12.50@7317.63,4042.81 cw(c7331.28,4029.15) 7331.28,4048.46 cw(c7331.28,4067.78) U12.50@7317.63,4054.12 ; U16.36@7317.63,4713.08 cw(c7326.38,4704.33) 7326.38,4716.71 ; U16.36@7317.63,4724.4 ccw(c7336.19,4742.96) 7336.19,4716.71 ; v1@7408.47,4256.76 ccw(c7392.26,4272.98) 7415.19,4272.98 ccw(c7438.13,4272.98) v1@7421.91,4256.76 ; v1@7411.3,4253.93 ccw(c7401.91,4263.32) 7415.19,4263.32 ccw(c7428.47,4263.32) v1@7419.08,4253.93 ; 5652.79,4163.43 cw(c5639.98,4150.63) 5658.09,4150.63 ccw(c5639.98,4150.63) 5652.79,4163.43 ; 5652.79,4163.43 ccw(c5665.59,4176.24) 5665.59,4158.13 cw(c5665.59,4176.24) 5652.79,4163.43
  Top Layer w8: v2(7731.89,4406.26) U7.G6@7751.58,4425.94 ; v2@7731.89,4415.26 ccw(c7731.89,4436.99) 7747.25,4421.62 ccw(c7762.62,4406.26) v2@7740.89,4406.26 ; U7.G6@7745.58,4425.94 cw(c7731.09,4425.94) 7741.33,4415.7 cw(c7751.58,4405.46) U7.G6@7751.58,4419.94
  MidLayer1 w4: v1(7345.19,4061.37) 7398.52,4114.71 7398.52,4166.71 7390.19,4175.04 7390.19,4225.04 v1(7415.19,4250.04) ; v1@7345.19,4066.87 ccw(c7345.19,4080.15) 7354.58,4070.76 ccw(c7363.97,4061.37) v1@7350.69,4061.37 ; v1@7345.19,4070.87 ccw(c7345.19,4093.81) 7361.41,4077.59 ccw(c7377.63,4061.37) v1@7354.69,4061.37 ; v1@7405.69,4250.04 cw(c7382.76,4250.04) 7398.97,4233.82 cw(c7415.19,4217.61) v1@7415.19,4240.54 ; v1@7409.69,4250.04 cw(c7396.41,4250.04) 7405.8,4240.65 cw(c7415.19,4231.26) v1@7415.19,4244.54
  MidLayer2 w4: v3@5666.24,4143.16 cw(c5667.82,4125.12) 5679.46,4138.99 cw(c5691.1,4152.86) v3@5673.06,4151.28 ; 5679.17,4139.24 ccw(c5689.1,4149.17) 5689.1,4135.12 5782.64,4135.12 5910,4135.12 5920,4135.12 5951.87,4135.12 6025.12,4208.37 6061.63,4208.37 6080,4190 6140.88,4190 6166.5,4164.37 6381.86,4164.37 6404.52,4141.71 6486.86,4141.71 6520.19,4175.04 6581.86,4175.04 6648.52,4108.37 6681.86,4108.37 6698.52,4091.71 6823.52,4091.71 6848.52,4116.71 6948.52,4116.71 6998.52,4066.71 6998.52,3970.37 7011.52,3957.37 7040.19,3957.37 7041.19,3958.37 7242.19,3958.37 v1(7345.19,4061.37) 7543.19,4061.37 7581.86,4100.04 7665.19,4100.04 7690.19,4075.04 7690.19,4058.37 7665.19,4033.37 7409.23,4033.37 7317.56,3941.71 7165.19,3941.71 7156.86,3933.37 7156.86,3907.37 7165.19,3899.04 7232.86,3899.04 7265.19,3866.71 7265.19,3587.04 7236.52,3558.37 7186.52,3558.37 7148.52,3520.37 7148.52,3161.35 7090.52,3103.35 7090.52,2837 7048.52,2795 7048.52,2733.37 v1(6993.52,2678.37) ; v1@6993.52,2683.87 ccw(c6993.52,2697.15) 7002.91,2687.76 ccw(c7012.3,2678.37) v1@6999.02,2678.37 ; v1@6993.52,2687.87 ccw(c6993.52,2710.81) 7009.74,2694.59 ccw(c7025.96,2678.37) v1@7003.02,2678.37 ; v1@7335.69,4061.37 cw(c7312.76,4061.37) 7328.97,4045.16 cw(c7345.19,4028.94) v1@7345.19,4051.87 ; v1@7339.69,4061.37 cw(c7326.41,4061.37) 7335.8,4051.99 cw(c7345.19,4042.6) v1@7345.19,4055.87 ; v1@7349.08,4057.49 cw(c7358.47,4048.1) 7358.47,4061.37 cw(c7358.47,4074.65) v1@7349.08,4065.26 ; v1@7351.91,4054.66 cw(c7368.13,4038.44) 7368.13,4061.37 cw(c7368.13,4084.31) v1@7351.91,4068.09 ; v1(7415.19,4250.04) 7440.19,4275.04 7648.52,4275.04 7665.19,4291.71 7665.19,4373.37 7678.52,4386.71 7712.34,4386.71 v2(7731.89,4406.26) ; v1@7415.19,4255.54 ccw(c7415.19,4268.82) 7424.58,4259.43 ccw(c7433.97,4250.04) v1@7420.69,4250.04 ; v1@7415.19,4259.54 ccw(c7415.19,4282.48) 7431.41,4266.26 ccw(c7447.63,4250.04) v1@7424.69,4250.04 ; v2@7720.89,4406.26 cw(c7694.33,4406.26) 7713.11,4387.48 cw(c7731.89,4368.7) v2@7731.89,4395.26 ; v2@7724.89,4406.26 cw(c7707.99,4406.26) 7719.94,4394.31 cw(c7731.89,4382.36) v2@7731.89,4399.26
  Bottom Layer w4: v1@6385.64,2635.05 ccw(c6381.47,2642.71) 6390.19,2642.71 ; v1(6390.19,2626.71) 6390.19,2642.71 ; v1@6394.74,2635.05 cw(c6398.91,2642.71) 6390.19,2642.71 ; v1@6986.81,2671.66 ccw(c6970.59,2655.44) 6970.59,2678.37 ccw(c6970.59,2701.31) v1@6986.81,2685.09 ; v1@6989.64,2674.49 ccw(c6980.25,2665.1) 6980.25,2678.37 ccw(c6980.25,2691.65) v1@6989.64,2682.26 ; v1(6993.52,2678.37) 6901.86,2678.37 6894.86,2671.37 6764.37,2671.37 6712.71,2723.04 6494.31,2723.04 6462.98,2691.71 6439.19,2691.71 6390.19,2642.71
DB_MEM.BUS_D14: U7.F6 U8.P22 U12.51 U16.37 U61.57 | length 6967.9
  Top Layer w4: U8.P22@5724.65,4162.81 cw(c5724.65,4144.71) 5737.45,4157.51 cw(c5750.25,4170.31) U8.P22@5732.15,4170.31 ; U8.P22@5724.65,4162.97 cw(c5724.65,4145.25) 5737.18,4157.78 cw(c5749.71,4170.31) U8.P22@5731.99,4170.31 ; U8.P22@5724.65,4170.31 v3(5744.33,4150.63) ; U61.57@6351.93,2646.31 6406.86,2646.31 6420.19,2632.97 v1(6420.19,2596.71) ; U61.57@6367.95,2643.48 cw(c6374.78,2636.65) 6374.78,2646.31 cw(c6374.78,2655.96) U61.57@6367.95,2649.13 ; v1@6413.47,2603.43 ccw(c6397.26,2619.64) 6420.19,2619.64 ccw(c6443.13,2619.64) v1@6426.91,2603.43 ; v1@6416.3,2600.6 ccw(c6406.91,2609.99) 6420.19,2609.99 ccw(c6433.47,2609.99) v1@6424.08,2600.6 ; v1(7248.52,4065.37) 7263.11,4079.96 ; U12.51@7269.89,4076.01 ccw(c7263.11,4072.16) 7263.11,4079.96 ; U12.51@7269.89,4083.91 cw(c7263.11,4087.76) 7263.11,4079.96 ; U16.37@7294.41,4750.24 U16.37@7311.96,4750.24 ; U16.37@7311.97,4746.24 cw(c7311.97,4709.15) 7338.19,4735.37 ; U16.37@7311.97,4754.24 cw(c7311.97,4736.47) 7324.53,4749.03 ; U12.51@7317.63,4074.3 cw(c7331.28,4060.65) 7331.28,4079.96 cw(c7331.28,4099.27) U12.51@7317.63,4085.62 ; 7331.36,4742.2 ccw(c7311.97,4722.81) U16.37@7311.97,4750.24 ; v1@7370.02,4147.37 cw(c7347.09,4147.37) 7363.31,4131.16 cw(c7379.52,4114.94) v1@7379.52,4137.87 ; v1@7374.02,4147.37 cw(c7360.75,4147.37) 7370.14,4137.99 cw(c7379.52,4128.6) v1@7379.52,4141.87 ; v1(7379.52,4147.37) 7345.52,4113.37 7345.52,4091.63 7333.86,4079.96 U12.51@7294.41,4079.96 7263.11,4079.96 ; v1(7431.86,4192.04) 7462.19,4222.37 7462.19,4502.19 7423.52,4540.86 7423.52,4560 7462.19,4598.67 7462.19,4775.06 7437.21,4800.04 7381.86,4800.04 7365.19,4783.37 7365.19,4750.04 7348.52,4733.37 7340.19,4733.37 7315.19,4758.37 7311.96,4758.37 U16.37@7311.96,4750.24 ; v1@7431.86,4197.54 ccw(c7431.86,4210.82) 7441.25,4201.43 ccw(c7450.64,4192.04) v1@7437.36,4192.04 ; v1@7431.86,4201.54 ccw(c7431.86,4224.48) 7448.07,4208.26 ccw(c7464.29,4192.04) v1@7441.36,4192.04 ; 5731.53,4163.43 cw(c5718.72,4150.63) 5736.83,4150.63 ccw(c5718.72,4150.63) 5731.53,4163.43 ; 5731.53,4163.43 ccw(c5744.33,4176.24) 5744.33,4158.13 cw(c5744.33,4176.24) 5731.53,4163.43
  Top Layer w8: v2(7771.26,4406.26) U7.F6@7790.95,4425.94 ; v2@7771.26,4415.26 ccw(c7771.26,4436.99) 7786.62,4421.62 ccw(c7801.99,4406.26) v2@7780.26,4406.26 ; U7.F6@7784.95,4425.94 cw(c7770.46,4425.94) 7780.7,4415.7 cw(c7790.95,4405.46) U7.F6@7790.95,4419.94
  MidLayer1 w4: v3@5744.98,4143.16 cw(c5746.56,4125.12) 5758.2,4138.99 cw(c5769.84,4152.86) v3@5751.8,4151.28 ; 5757.91,4139.24 ccw(c5767.84,4149.17) 5767.84,4135.12 5861.38,4135.12 5910,4135.12 5920,4135.12 5924.74,4135.12 5936.86,4135.12 5960.11,4158.37 6073.52,4158.37 6090.19,4175.04 v1(6090.19,4208.37) ; v1@6083.47,4201.66 cw(c6067.26,4185.44) 6090.19,4185.44 cw(c6113.13,4185.44) v1@6096.91,4201.66 ; v1@6086.3,4204.49 cw(c6076.91,4195.1) 6090.19,4195.1 cw(c6103.47,4195.1) v1@6094.08,4204.49 ; v1(6998.52,2766.71) 7059.82,2828 7172.89,2828 7248.52,2903.63 7248.52,3010 7248.52,3064.34 7282.19,3098 7282.19,3849.71 7273.52,3858.37 7231.86,3900.04 7231.86,3922.71 7248.52,3939.37 v1(7248.52,4065.37) ; v1@6998.52,2772.21 ccw(c6998.52,2785.49) 7007.91,2776.1 ccw(c7017.3,2766.71) v1@7004.02,2766.71 ; v1@6998.52,2776.21 ccw(c6998.52,2799.14) 7014.74,2782.93 ccw(c7030.96,2766.71) v1@7008.02,2766.71 ; v1@7241.81,4058.66 cw(c7225.59,4042.44) 7248.52,4042.44 cw(c7271.46,4042.44) v1@7255.24,4058.66 ; v1@7244.64,4061.49 cw(c7235.25,4052.1) 7248.52,4052.1 cw(c7261.8,4052.1) v1@7252.41,4061.49
  MidLayer2 w4: v1(7431.86,4192.04) 7682.19,4192.04 7752.19,4262.04 7752.19,4387.19 v2(7771.26,4406.26) ; v1@7435.75,4188.15 cw(c7445.14,4178.76) 7445.14,4192.04 cw(c7445.14,4205.32) v1@7435.75,4195.93 ; v1@7438.57,4185.32 cw(c7454.79,4169.11) 7454.79,4192.04 cw(c7454.79,4214.98) v1@7438.57,4198.76 ; v2@7760.26,4406.26 cw(c7733.7,4406.26) 7752.48,4387.48 cw(c7771.26,4368.7) v2@7771.26,4395.26 ; v2@7764.26,4406.26 cw(c7747.36,4406.26) 7759.31,4394.31 cw(c7771.26,4382.36) v2@7771.26,4399.26
  Bottom Layer w4: v1@6090.19,4198.87 cw(c6090.19,4175.94) 6106.41,4192.16 cw(c6122.63,4208.37) v1@6099.69,4208.37 ; v1@6090.19,4202.87 cw(c6090.19,4189.6) 6099.58,4198.99 cw(c6108.97,4208.37) v1@6095.69,4208.37 ; v1(6090.19,4208.37) 6106.86,4191.71 6156.86,4191.71 6184.19,4164.37 6400.86,4164.37 6415.19,4150.04 6481.86,4150.04 6508.19,4176.37 6698.52,4176.37 6732.86,4142.04 6981.04,4142.04 6993.5,4142.04 7035.5,4184.04 7342.86,4184.04 7351.86,4175.04 v1(7379.52,4147.37) 7424.19,4192.04 v1(7431.86,4192.04) ; v1(6420.19,2596.71) 6420.19,2605.04 6450.52,2635.37 6481.86,2635.37 6492.19,2625.04 6672.52,2625.04 6710.86,2663.37 6895,2663.37 6900,2658.37 6998.52,2658.37 7015.19,2675.04 7015.19,2750.04 v1(6998.52,2766.71) ; v1@6421.69,2596.71 cw(c6445.43,2596.71) 6428.64,2613.49 ; v1@6425.69,2596.71 cw(c6459.09,2596.71) 6435.47,2620.32 ; v1@6429.69,2596.71 cw(c6472.74,2596.71) 6442.3,2627.15 ; v1@6998.52,2757.21 cw(c6998.52,2734.27) 7014.74,2750.49 cw(c7030.96,2766.71) v1@7008.02,2766.71 ; v1@6998.52,2761.21 cw(c6998.52,2747.93) 7007.91,2757.32 cw(c7017.3,2766.71) v1@7004.02,2766.71 ; v1@7370.02,4147.37 ccw(c7347.09,4147.37) 7363.31,4163.59 ccw(c7379.52,4179.81) 7379.52,4156.87 ccw(c7379.52,4179.81) 7395.74,4163.59 ccw(c7411.96,4147.37) v1@7389.02,4147.37 ; v1@7374.02,4147.37 ccw(c7360.75,4147.37) 7370.13,4156.76 ccw(c7379.52,4166.15) 7379.52,4152.87 ccw(c7379.52,4166.15) 7388.91,4156.76 ccw(c7398.3,4147.37) v1@7385.02,4147.37 ; 7402.55,4170.4 cw(c7431.86,4141.1) v1@7431.86,4182.54 ; 7409.38,4177.23 cw(c7431.86,4154.75) v1@7431.86,4186.54 ; 7416.21,4184.06 cw(c7431.86,4168.41) v1@7431.86,4190.54
DB_MEM.BUS_D15: U7.G7 U8.P26 U12.53 U16.38 U61.58 | length 6483
  Top Layer w4: U8.P26@5882.13,4170.31 5910,4170.31 5920,4170.31 6010,4170.31 6023.06,4183.37 v1(6056.86,4183.37) ; U8.P26@5887.32,4165.12 cw(c5899.85,4152.59) 5899.85,4170.31 cw(c5899.85,4188.04) U8.P26@5887.32,4175.51 ; U8.P26@5887.43,4165.01 cw(c5900.23,4152.21) 5900.23,4170.31 cw(c5900.23,4188.42) U8.P26@5887.43,4175.62 ; v1@6050.14,4176.66 ccw(c6033.92,4160.44) 6033.92,4183.37 ccw(c6033.92,4206.31) v1@6050.14,4190.09 ; v1@6052.97,4179.49 ccw(c6043.58,4170.1) 6043.58,4183.37 ccw(c6043.58,4196.65) v1@6052.97,4187.26 ; v1(6190.19,2516.71) 6215,2541.52 6215,2560 6320.99,2665.99 U61.58@6351.93,2665.99 ; v1@6190.19,2522.21 ccw(c6190.19,2535.49) 6199.58,2526.1 ccw(c6208.97,2516.71) v1@6195.69,2516.71 ; v1@6190.19,2526.21 ccw(c6190.19,2549.14) 6206.41,2532.93 ccw(c6222.63,2516.71) v1@6199.69,2516.71 ; U61.58@6335.91,2663.16 ccw(c6329.08,2656.33) 6329.08,2665.99 ccw(c6329.08,2675.65) U61.58@6335.91,2668.82 ; v1(7246.52,4125.04) 7264.44,4142.95 ; v1@7246.52,4130.54 ccw(c7246.52,4143.82) 7255.91,4134.43 ccw(c7265.3,4125.04) v1@7252.02,4125.04 ; v1@7246.52,4134.54 ccw(c7246.52,4157.48) 7262.74,4141.26 ccw(c7278.96,4125.04) v1@7256.02,4125.04 ; U12.53@7269.57,4139.65 ccw(c7264.44,4137.32) 7264.44,4142.95 ; U12.53@7269.57,4146.26 cw(c7264.44,4148.59) 7264.44,4142.95 ; U16.38@7294.41,4781.73 7332.19,4781.73 7340.19,4773.73 v1(7340.19,4758.37) ; U12.53@7314.35,4146.17 ccw(c7318.06,4151.16) 7322.45,4146.76 ; U12.53@7316.74,4149.38 ccw(c7320.85,4154.92) 7325.73,4150.04 ; U16.38@7317.63,4776.08 cw(c7331.28,4762.42) 7331.28,4781.73 cw(c7331.28,4801.05) U16.38@7317.63,4787.39 ; U12.53@7319.73,4141.03 cw(c7322.19,4140.42) 7322.19,4142.95 ; U12.53@7319.73,4144.87 ccw(c7322.19,4145.48) 7322.19,4142.95 ; 7322.96,4147.26 cw(c7331.1,4139.11) v1@7337.37,4148.78 ; 7326.45,4150.76 cw(c7333.85,4143.36) v1@7339.55,4152.14 ; v1(7338.19,4150.04) 7325.74,4150.04 ; 7264.44,4142.95 7322.19,4142.95 ; 7322.19,4142.95 7322.19,4146.5 7325.74,4150.04
  Top Layer w8: v2(7731.89,4366.89) U7.G7@7751.57,4386.57 ; v2@7731.89,4375.89 ccw(c7731.89,4397.62) 7747.25,4382.25 ccw(c7762.62,4366.89) v2@7740.89,4366.89 ; U7.G7@7745.57,4386.57 cw(c7731.09,4386.57) 7741.33,4376.33 cw(c7751.57,4366.09) U7.G7@7751.57,4380.57
  MidLayer1 w4: v1@6548.14,2460.09 ccw(c6531.92,2476.31) 6554.86,2476.31 ccw(c6577.79,2476.31) v1@6561.57,2460.09 ; v1@6550.97,2457.26 ccw(c6541.58,2466.65) 6554.86,2466.65 ccw(c6568.14,2466.65) v1@6558.75,2457.26 ; v1(6554.86,2453.37) 6554.86,2478.39 6790.19,2713.73 6790.19,2794.08 7274.19,3278.08 7274.19,3846.37 7223.52,3897.04 7223.52,3958.37 7231.86,3966.71 7231.86,4008.37 7223.52,4016.71 7223.52,4102.04 v1(7246.52,4125.04) 7246.52,4293.73 7281.86,4329.06 7281.86,4746.86 7293.37,4758.37 v1(7340.19,4758.37) ; v1@7237.02,4125.04 cw(c7214.09,4125.04) 7230.31,4108.82 cw(c7246.52,4092.61) v1@7246.52,4115.54 ; v1@7239.81,4131.76 ccw(c7223.59,4147.98) 7246.52,4147.98 ccw(c7269.46,4147.98) v1@7253.24,4131.76 ; v1@7241.02,4125.04 cw(c7227.75,4125.04) 7237.14,4115.65 cw(c7246.52,4106.26) v1@7246.52,4119.54 ; v1@7242.64,4128.93 ccw(c7233.25,4138.32) 7246.52,4138.32 ccw(c7259.8,4138.32) v1@7250.41,4128.93 ; v1@7333.47,4751.66 ccw(c7317.26,4735.44) 7317.26,4758.37 ccw(c7317.26,4781.31) v1@7333.47,4765.09 ; v1@7336.3,4754.49 ccw(c7326.91,4745.1) 7326.91,4758.37 ccw(c7326.91,4771.65) v1@7336.3,4762.26
  MidLayer2 w4: v1(7338.19,4150.04) 7413.19,4225.04 7433.52,4225.04 7458.52,4250.04 7687.86,4250.04 7712.78,4274.97 7712.78,4347.78 7713.04,4347.78 7722.38,4357.12 7722.38,4357.37 v2(7731.89,4366.89) ; v1@7338.19,4155.54 ccw(c7338.19,4168.82) 7347.58,4159.43 ccw(c7356.97,4150.04) v1@7343.69,4150.04 ; v1@7338.19,4159.54 ccw(c7338.19,4182.48) 7354.41,4166.26 ccw(c7370.63,4150.04) v1@7347.69,4150.04 ; 7713.17,4347.91 ccw(c7694.53,4366.55) v2@7720.89,4366.79 ; 7713.55,4348.29 cw(c7731.89,4329.96) v2@7731.89,4355.89 ; 7719.91,4354.65 ccw(c7707.9,4366.67) v2@7724.89,4366.83 ; 7720.38,4355.12 cw(c7731.89,4343.62) v2@7731.89,4359.89
  Bottom Layer w4: v1(6056.86,4183.37) 6153.88,4183.37 6181.54,4155.71 6392.86,4155.71 6423.52,4125.04 6472.19,4125.04 6514.86,4167.71 6580.86,4167.71 6613.86,4134.71 6710.67,4134.71 ; v1@6060.75,4179.49 cw(c6070.14,4170.1) 6070.14,4183.37 cw(c6070.14,4196.65) v1@6060.75,4187.26 ; v1@6063.57,4176.66 cw(c6079.79,4160.44) 6079.79,4183.37 cw(c6079.79,4206.31) v1@6063.57,4190.09 ; v1@6190.19,2507.21 cw(c6190.19,2484.27) 6206.41,2500.49 cw(c6222.63,2516.71) v1@6199.69,2516.71 ; v1@6190.19,2511.21 cw(c6190.19,2497.93) 6199.58,2507.32 cw(c6208.97,2516.71) v1@6195.69,2516.71 ; v1(6190.19,2516.71) 6231.86,2475.04 6263.52,2475.04 6280.19,2458.37 6428.88,2458.37 6462.21,2491.71 6516.52,2491.71 v1(6554.86,2453.37) ; v1@6545.36,2453.37 ccw(c6522.42,2453.37) 6538.64,2469.59 ccw(c6554.86,2485.81) v1@6554.86,2462.87 ; v1@6549.36,2453.37 ccw(c6536.08,2453.37) 6545.47,2462.76 ccw(c6554.86,2472.15) v1@6554.86,2458.87 ; 6710.67,4134.04 7216,4134.04 7225,4125.04 ; v1@7239.51,4118.64 ccw(c7225,4105.41) 7225,4125.04 ; v1@7239.51,4131.44 cw(c7225,4144.67) 7225,4125.04 ; v1@7242.46,4121.33 ccw(c7234.06,4113.68) 7234.06,4125.04 ccw(c7234.06,4136.41) v1@7242.46,4128.75 ; v1(7246.52,4125.04) 7225,4125.04
DB_MEM.BUS_D16: U8.P18 U13.2 U17.7 U61.60 | length 4072.6
  Top Layer w4: U8.P18@5567.17,4162.81 cw(c5567.17,4144.71) 5579.97,4157.51 cw(c5592.77,4170.31) U8.P18@5574.67,4170.31 ; U8.P18@5567.17,4162.97 cw(c5567.17,4145.25) 5579.7,4157.78 cw(c5592.23,4170.31) U8.P18@5574.51,4170.31 ; U8.P18@5567.17,4170.31 v3(5586.85,4150.63) ; v1(6090.19,4125.04) 6117.24,4125.04 6124.57,4132.37 6135,4132.37 6145.58,4142.95 U13.2@6170.59,4142.95 ; v1@6094.08,4121.15 cw(c6103.47,4111.76) 6103.47,4125.04 cw(c6103.47,4138.32) v1@6094.08,4128.93 ; v1@6096.91,4118.32 cw(c6113.13,4102.11) 6113.13,4125.04 cw(c6113.13,4147.98) v1@6096.91,4131.76 ; 6136.71,4134.08 cw(c6149.26,4121.53) U13.2@6152.34,4139.01 ; 6142.14,4139.52 cw(c6150.89,4130.77) U13.2@6153.03,4142.95 ; U17.7@6170.59,4781.73 6193.02,4781.73 6205,4793.71 ; U17.7@6189.09,4785.62 ccw(c6191.81,4796.82) 6199.96,4788.67 ; U17.7@6190.04,4789.51 ccw(c6193.78,4804.93) 6205,4793.71 ; U17.7@6196.15,4781.73 cw(c6203.7,4781.73) 6198.36,4787.07 ; U61.60@6351.93,2705.36 6378.84,2705.36 v1(6398.52,2725.04) ; U61.60@6367.95,2702.53 cw(c6374.78,2695.7) 6374.78,2705.36 cw(c6374.78,2715.02) U61.60@6367.95,2708.19 ; v1@6375.14,4090.09 ccw(c6357.31,4107.92) 6382.52,4107.92 ; v1@6377.97,4087.26 ccw(c6366.97,4098.26) 6382.52,4098.26 ; v1(6381.86,4083.37) 6382.52,4084.04 6382.52,4415.04 6398.52,4431.04 6398.52,4608.37 6373.52,4633.37 6373.52,4741.37 6321.19,4793.71 6205,4793.71 ; 6382.52,4095.04 ccw(c6393.53,4095.04) v1@6385.75,4087.26 ; 6382.52,4104.7 ccw(c6403.18,4104.7) v1@6388.57,4090.09 ; v1@6389.02,2725.04 cw(c6366.09,2725.04) 6382.31,2708.82 cw(c6398.52,2692.61) v1@6398.52,2715.54 ; v1@6393.02,2725.04 cw(c6379.75,2725.04) 6389.13,2715.65 cw(c6398.52,2706.26) v1@6398.52,2719.54 ; 5574.05,4163.43 cw(c5561.24,4150.63) 5579.35,4150.63 ccw(c5561.24,4150.63) 5574.05,4163.43 ; 5574.05,4163.43 ccw(c5586.85,4176.24) 5586.85,4158.13 cw(c5586.85,4176.24) 5574.05,4163.43
  MidLayer1 w4: v1(6381.86,4083.37) 6383.52,4085.04 6490.19,4085.04 6497.19,4078.04 6497.19,3673.71 6490.19,3666.71 6490.19,3375.37 6448.52,3333.71 6448.52,3242.71 6456.86,3234.37 6456.86,3217.71 6448.52,3209.37 6425.19,3209.37 6422.86,3207.04 6422.86,2995.37 6455,2963.23 6455,2813.09 6415.19,2773.28 6415.19,2741.71 v1(6398.52,2725.04) ; v1@6385.75,4079.49 cw(c6399.16,4066.07) 6399.16,4085.04 ; v1@6388.57,4076.66 cw(c6408.81,4056.42) 6408.81,4085.04 ; v1@6388.57,4090.09 ccw(c6400.77,4102.29) 6400.77,4085.04 ; v1@6398.52,2730.54 ccw(c6398.52,2743.82) 6407.91,2734.43 ccw(c6417.3,2725.04) v1@6404.02,2725.04 ; v1@6398.52,2734.54 ccw(c6398.52,2757.48) 6414.74,2741.26 ccw(c6430.96,2725.04) v1@6408.02,2725.04
  MidLayer2 w4: v1(6090.19,4125.04) 6117.24,4125.04 6124.57,4132.37 6132.86,4132.37 6161.52,4103.71 6234.86,4103.71 6239.52,4099.04 6308.85,4099.04 6312.62,4102.81 6327.38,4102.81 6331.15,4099.04 6366.19,4099.04 v1(6381.86,4083.37) ; v1@6094.08,4121.15 cw(c6103.47,4111.76) 6103.47,4125.04 cw(c6103.47,4138.32) v1@6094.08,4128.93 ; v1@6096.91,4118.32 cw(c6113.13,4102.11) 6113.13,4125.04 cw(c6113.13,4147.98) v1@6096.91,4131.76
  Bottom Layer w4: v3@5587.5,4143.16 cw(c5589.08,4125.12) 5600.72,4138.99 cw(c5612.36,4152.86) v3@5594.32,4151.28 ; 5600.43,4139.24 ccw(c5610.36,4149.17) 5610.36,4135.12 5703.9,4135.12 5910,4135.12 5920,4135.12 5951.87,4135.12 5966.79,4150.04 6065.19,4150.04 v1(6090.19,4125.04) ; v1@6080.69,4125.04 ccw(c6057.76,4125.04) 6073.97,4141.26 ccw(c6090.19,4157.48) v1@6090.19,4134.54 ; v1@6084.69,4125.04 ccw(c6071.41,4125.04) 6080.8,4134.43 ccw(c6090.19,4143.82) v1@6090.19,4130.54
